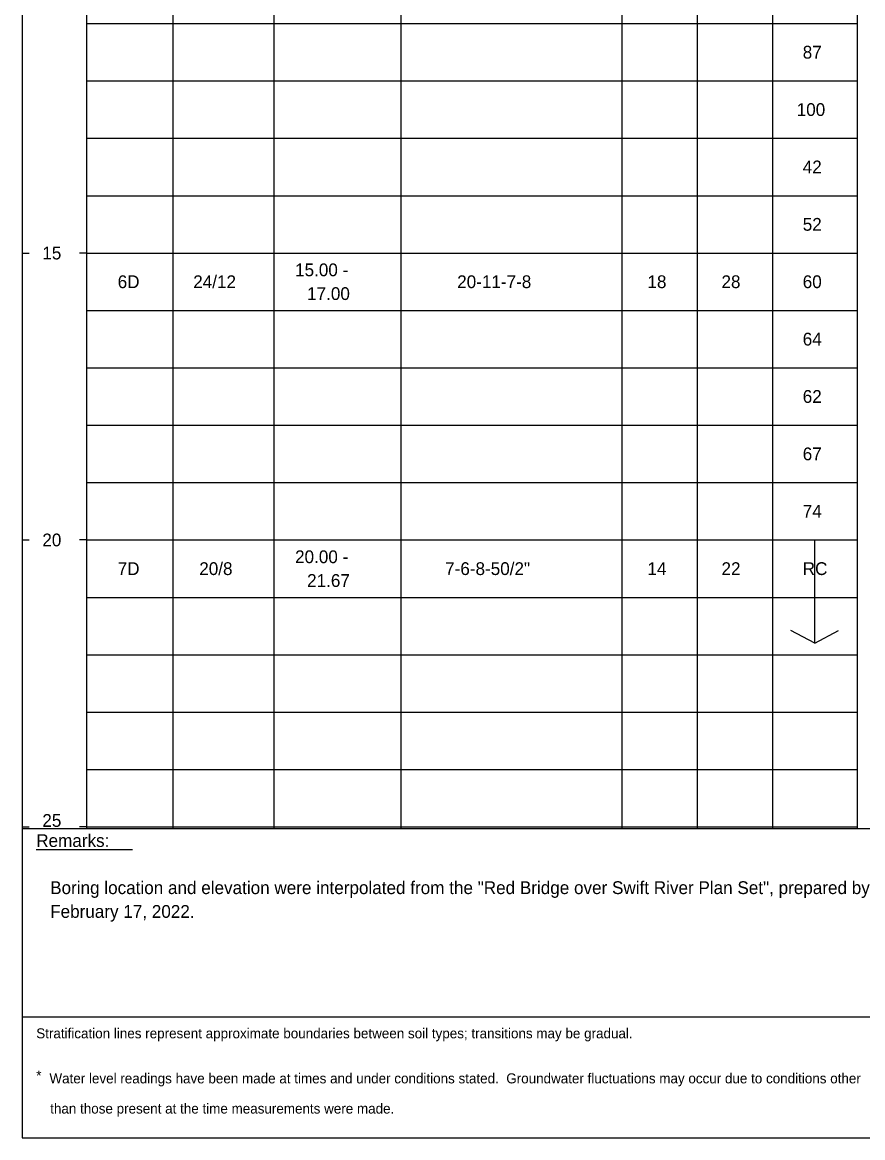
# Model space of a CAD drawing. Extents: x 9422 to 9552, y 6780 to 6860.
# Drawn here: x 9498.16 to 9512.81, y 6816.55 to 6835.99 of the extents above; entities that cross this region are included whole.
import ezdxf

# ---------------------------------------------------------------- set-up
doc = ezdxf.new("R2010")
doc.units = 0
doc.layers.add('7', color=7, linetype='Continuous')

msp = doc.modelspace()

# ---------------------------------------------------------------- linework, layer by layer
at = {"layer": '7'}
for p, q in [((9511.973, 6825.168), (9511.973, 6826.968)), ((9511.973, 6825.168), (9511.556, 6825.393)), ((9511.973, 6825.168), (9512.389, 6825.393)), ((9498.401, 6821.572), (9500.079, 6821.572))]:
    msp.add_line(p, q, dxfattribs=at)
for points in [[(9498.158, 6860.072), (9498.158, 6816.552)], [(9499.276, 6850.486), (9499.276, 6821.941)], [(9500.785, 6849.95), (9500.785, 6821.941)], [(9502.54, 6849.95), (9502.54, 6821.941)], [(9504.755, 6849.95), (9504.755, 6821.941)], [(9508.61, 6849.95), (9508.61, 6821.941)], [(9509.922, 6849.95), (9509.922, 6821.941)], [(9511.234, 6849.95), (9511.234, 6821.941)], [(9512.711, 6849.95), (9512.711, 6821.941)], [(9499.276, 6835.968), (9500.785, 6835.968)], [(9500.785, 6835.968), (9502.54, 6835.968)], [(9502.54, 6835.968), (9504.755, 6835.968)], [(9504.755, 6835.968), (9508.61, 6835.968)], [(9508.61, 6835.968), (9509.922, 6835.968)], [(9509.922, 6835.968), (9511.234, 6835.968)], [(9511.234, 6835.968), (9512.711, 6835.968)], [(9499.276, 6834.968), (9500.785, 6834.968)], [(9500.785, 6834.968), (9502.54, 6834.968)], [(9502.54, 6834.968), (9504.755, 6834.968)], [(9504.755, 6834.968), (9508.61, 6834.968)], [(9508.61, 6834.968), (9509.922, 6834.968)], [(9509.922, 6834.968), (9511.234, 6834.968)], [(9511.234, 6834.968), (9512.711, 6834.968)], [(9499.276, 6833.968), (9500.785, 6833.968)], [(9500.785, 6833.968), (9502.54, 6833.968)], [(9502.54, 6833.968), (9504.755, 6833.968)], [(9504.755, 6833.968), (9508.61, 6833.968)], [(9508.61, 6833.968), (9509.922, 6833.968)], [(9509.922, 6833.968), (9511.234, 6833.968)], [(9511.234, 6833.968), (9512.711, 6833.968)], [(9499.276, 6832.968), (9500.785, 6832.968)], [(9500.785, 6832.968), (9502.54, 6832.968)], [(9502.54, 6832.968), (9504.755, 6832.968)], [(9504.755, 6832.968), (9508.61, 6832.968)], [(9508.61, 6832.968), (9509.922, 6832.968)], [(9509.922, 6832.968), (9511.234, 6832.968)], [(9511.234, 6832.968), (9512.711, 6832.968)], [(9498.158, 6831.968), (9498.279, 6831.968)], [(9499.276, 6831.968), (9499.154, 6831.968)], [(9499.276, 6831.968), (9500.785, 6831.968)], [(9500.785, 6831.968), (9502.54, 6831.968)], [(9502.54, 6831.968), (9504.755, 6831.968)], [(9504.755, 6831.968), (9508.61, 6831.968)], [(9508.61, 6831.968), (9509.922, 6831.968)], [(9509.922, 6831.968), (9511.234, 6831.968)], [(9511.234, 6831.968), (9512.711, 6831.968)], [(9499.276, 6830.968), (9500.785, 6830.968)], [(9500.785, 6830.968), (9502.54, 6830.968)], [(9502.54, 6830.968), (9504.755, 6830.968)], [(9504.755, 6830.968), (9508.61, 6830.968)], [(9508.61, 6830.968), (9509.922, 6830.968)], [(9509.922, 6830.968), (9511.234, 6830.968)], [(9511.234, 6830.968), (9512.711, 6830.968)], [(9499.276, 6829.968), (9500.785, 6829.968)], [(9500.785, 6829.968), (9502.54, 6829.968)], [(9502.54, 6829.968), (9504.755, 6829.968)], [(9504.755, 6829.968), (9508.61, 6829.968)], [(9508.61, 6829.968), (9509.922, 6829.968)], [(9509.922, 6829.968), (9511.234, 6829.968)], [(9511.234, 6829.968), (9512.711, 6829.968)], [(9499.276, 6828.968), (9500.785, 6828.968)], [(9500.785, 6828.968), (9502.54, 6828.968)], [(9502.54, 6828.968), (9504.755, 6828.968)], [(9504.755, 6828.968), (9508.61, 6828.968)], [(9508.61, 6828.968), (9509.922, 6828.968)], [(9509.922, 6828.968), (9511.234, 6828.968)], [(9511.234, 6828.968), (9512.711, 6828.968)], [(9499.276, 6827.968), (9500.785, 6827.968)], [(9500.785, 6827.968), (9502.54, 6827.968)], [(9502.54, 6827.968), (9504.755, 6827.968)], [(9504.755, 6827.968), (9508.61, 6827.968)], [(9508.61, 6827.968), (9509.922, 6827.968)], [(9509.922, 6827.968), (9511.234, 6827.968)], [(9511.234, 6827.968), (9512.711, 6827.968)], [(9498.158, 6826.968), (9498.279, 6826.968)], [(9499.276, 6826.968), (9499.154, 6826.968)], [(9499.276, 6826.968), (9500.785, 6826.968)], [(9500.785, 6826.968), (9502.54, 6826.968)], [(9502.54, 6826.968), (9504.755, 6826.968)], [(9504.755, 6826.968), (9508.61, 6826.968)], [(9508.61, 6826.968), (9509.922, 6826.968)], [(9509.922, 6826.968), (9511.234, 6826.968)], [(9511.234, 6826.968), (9512.711, 6826.968)], [(9499.276, 6825.968), (9500.785, 6825.968)], [(9500.785, 6825.968), (9502.54, 6825.968)], [(9502.54, 6825.968), (9504.755, 6825.968)], [(9504.755, 6825.968), (9508.61, 6825.968)], [(9508.61, 6825.968), (9509.922, 6825.968)], [(9509.922, 6825.968), (9511.234, 6825.968)], [(9511.234, 6825.968), (9512.711, 6825.968)], [(9499.276, 6824.968), (9500.785, 6824.968)], [(9500.785, 6824.968), (9502.54, 6824.968)], [(9502.54, 6824.968), (9504.755, 6824.968)], [(9504.755, 6824.968), (9508.61, 6824.968)], [(9508.61, 6824.968), (9509.922, 6824.968)], [(9509.922, 6824.968), (9511.234, 6824.968)], [(9511.234, 6824.968), (9512.711, 6824.968)], [(9499.276, 6823.968), (9500.785, 6823.968)], [(9500.785, 6823.968), (9502.54, 6823.968)], [(9502.54, 6823.968), (9504.755, 6823.968)], [(9504.755, 6823.968), (9508.61, 6823.968)], [(9508.61, 6823.968), (9509.922, 6823.968)], [(9509.922, 6823.968), (9511.234, 6823.968)], [(9511.234, 6823.968), (9512.711, 6823.968)], [(9499.276, 6822.968), (9500.785, 6822.968)], [(9500.785, 6822.968), (9502.54, 6822.968)], [(9502.54, 6822.968), (9504.755, 6822.968)], [(9504.755, 6822.968), (9508.61, 6822.968)], [(9508.61, 6822.968), (9509.922, 6822.968)], [(9509.922, 6822.968), (9511.234, 6822.968)], [(9511.234, 6822.968), (9512.711, 6822.968)], [(9498.158, 6821.968), (9498.279, 6821.968)], [(9498.158, 6821.941), (9529.654, 6821.941)], [(9499.276, 6821.968), (9499.154, 6821.968)], [(9499.276, 6821.968), (9500.785, 6821.968)], [(9500.785, 6821.968), (9502.54, 6821.968)], [(9502.54, 6821.968), (9504.755, 6821.968)], [(9504.755, 6821.968), (9508.61, 6821.968)], [(9508.61, 6821.968), (9509.922, 6821.968)], [(9509.922, 6821.968), (9511.234, 6821.968)], [(9511.234, 6821.968), (9512.711, 6821.968)], [(9498.158, 6818.66), (9529.654, 6818.66)], [(9498.158, 6816.552), (9529.654, 6816.552)]]:
    msp.add_lwpolyline(points, dxfattribs=at)

# ---------------------------------------------------------------- texts
for s, height, p in [('87', 0.2228, (9511.763, 6835.357)), ('100', 0.2228, (9511.658, 6834.357)), ('42', 0.2228, (9511.763, 6833.357)), ('52', 0.2228, (9511.763, 6832.357)), ('15', 0.2228, (9498.507, 6831.857)), ('15.00 -', 0.2228, (9502.913, 6831.564)), ('6D', 0.2228, (9499.821, 6831.357)), ('24/12', 0.2228, (9501.138, 6831.357)), ('20-11-7-8', 0.2228, (9505.739, 6831.357)), ('18', 0.2228, (9509.056, 6831.357)), (' 28', 0.2228, (9510.264, 6831.357)), ('60', 0.2228, (9511.763, 6831.357)), ('17.00', 0.2228, (9503.123, 6831.15)), ('64', 0.2228, (9511.763, 6830.357)), ('62', 0.2228, (9511.763, 6829.357)), ('67', 0.2228, (9511.763, 6828.357)), ('74', 0.2228, (9511.763, 6827.357)), ('20', 0.2228, (9498.507, 6826.857)), ('20.00 -', 0.2228, (9502.913, 6826.564)), ('7D', 0.2228, (9499.821, 6826.357)), ('20/8', 0.2228, (9501.243, 6826.357)), ('7-6-8-50/2"', 0.2228, (9505.529, 6826.357)), ('14', 0.2228, (9509.056, 6826.357)), (' 22', 0.2228, (9510.264, 6826.357)), ('RC', 0.2228, (9511.763, 6826.357)), ('21.67', 0.2228, (9503.123, 6826.15)), ('25', 0.2228, (9498.507, 6821.968)), ('Remarks:', 0.2228, (9498.401, 6821.618)), ('Boring location and elevation were interpolated from the "Red Bridge over Swift River Plan Set", prepared by the TY Lin International, last dated', 0.222801, (9498.644, 6820.797)), ('February 17, 2022.', 0.2228, (9498.644, 6820.383)), ('Stratification lines represent approximate boundaries between soil types; transitions may be gradual.', 0.175058, (9498.401, 6818.283)), ('*', 0.175, (9498.401, 6817.547)), (' Water level readings have been made at times and under conditions stated.  Groundwater fluctuations may occur due to conditions other', 0.175058, (9498.566, 6817.498)), ('than those present at the time measurements were made.', 0.17506, (9498.644, 6816.972))]:
    msp.add_text(s, height=height, dxfattribs=at).set_placement(p)

doc.saveas('drawing.dxf')
